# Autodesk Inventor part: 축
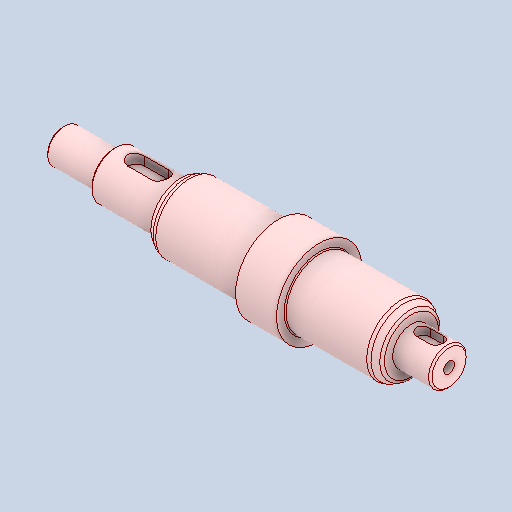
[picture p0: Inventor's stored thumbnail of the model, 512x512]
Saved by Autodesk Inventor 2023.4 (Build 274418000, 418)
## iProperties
Created: 2024-04
Part Number: 축
Material: 강철, 연강
Document SubType Name: Modeling
Designer: EDU
Density: 7.86 g/cm^3
Appearance: 기본값
Author: jhkim
Sending System: Autodesk Inventor 2025
Preprocessor: ST-DEVELOPER v20
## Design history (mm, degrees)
node "축1"
node "솔리드2"
node "솔리드1"
